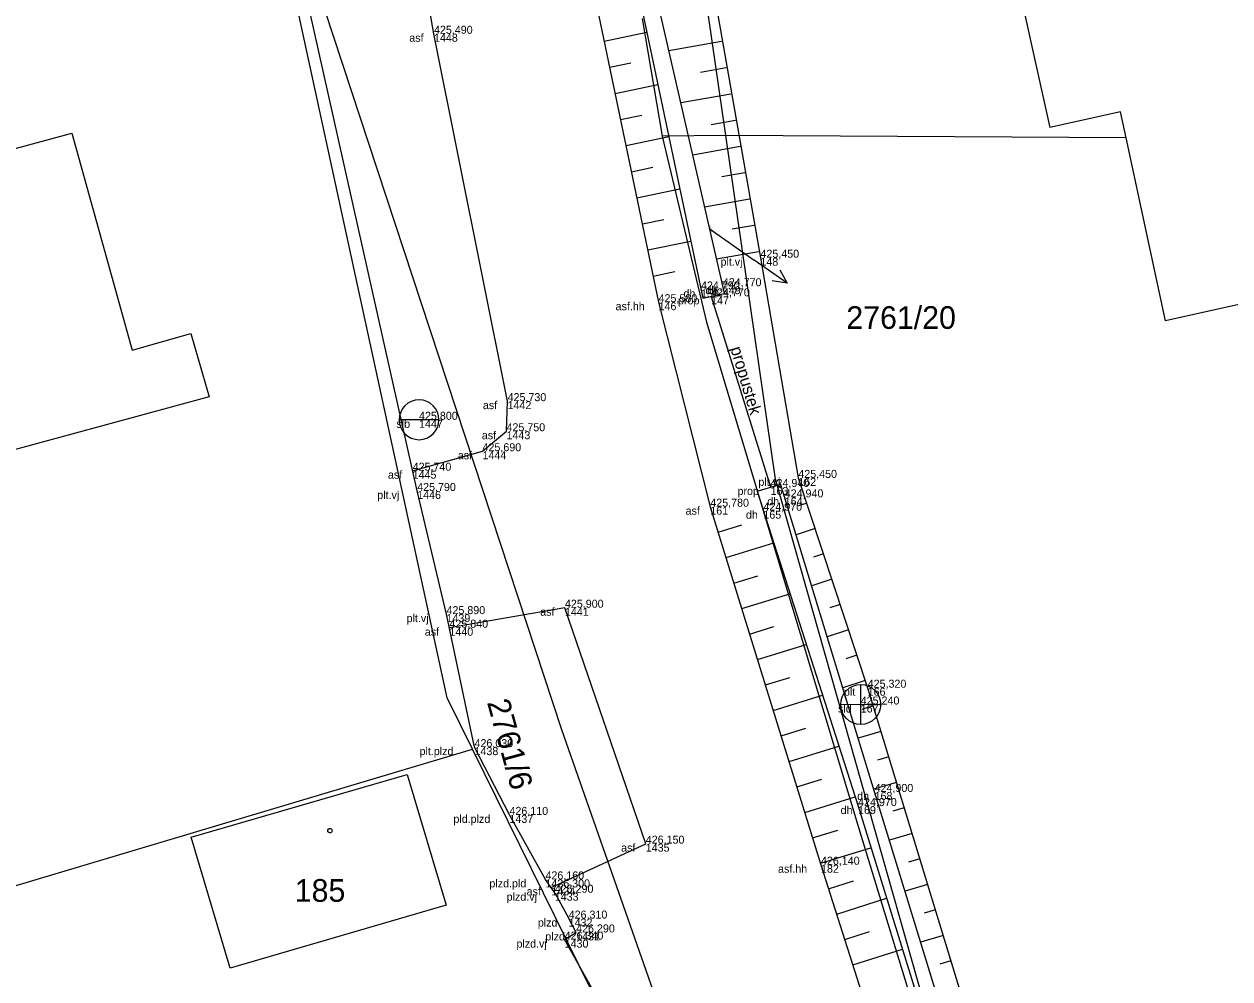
# Model space of a CAD drawing. Extents: x -747792 to -745414, y -1093712 to -1091463.
# Drawn here: x -746644.57 to -746599.36, y -1092850.41 to -1092814.6 of the extents above; entities that cross this region are included whole.
import ezdxf

# ---------------------------------------------------------------- set-up
doc = ezdxf.new("R2010")
doc.units = 0
for name, color, linetype in [('Doplňkové značky', 7, 'Continuous'), ('Hladina', 7, 'Continuous'), ('Koleje_dopravní prvky', 7, 'Continuous'), ('Nezařazené objekty', 7, 'Continuous'), ('Nivelační značky_hrany', 7, 'Continuous'), ('Ploty_opěrné zdi', 7, 'Continuous'), ('Pracovní_bod PPBP', 7, 'Continuous'), ('Pracovní_bod PPBP - výška', 7, 'Continuous'), ('Pracovní_bod ZPBP', 7, 'Continuous'), ('Pracovní_bod ZPBP - číslo', 7, 'Continuous'), ('Rozhraní ploch', 7, 'Continuous'), ('Stromy_porost', 7, 'Continuous'), ('Výškopis', 7, 'Continuous'), ('Čísla popisná_parcelní', 7, 'Continuous')]:
    doc.layers.add(name, color=color, linetype=linetype)

msp = doc.modelspace()

# ---------------------------------------------------------------- linework, layer by layer
at = {"layer": 'Doplňkové značky'}
for points in [[(-746618.85, -1092822.29), (-746617.19, -1092823.45)], [(-746615.963, -1092824.313), (-746617.19, -1092823.45)], [(-746616.228, -1092823.821), (-746615.963, -1092824.313), (-746616.516, -1092824.23)]]:
    msp.add_lwpolyline(points, dxfattribs=at)
at = {"layer": 'Hladina'}
for p, q in [((-746629.2, -1092814.96), (-746629.2, -1092814.96)), ((-746616.96, -1092823.36), (-746616.96, -1092823.36)), ((-746618.37, -1092824.43), (-746618.37, -1092824.43)), ((-746619.19, -1092824.55), (-746619.19, -1092824.55)), ((-746618.81, -1092824.81), (-746618.81, -1092824.81)), ((-746620.78, -1092825.03), (-746620.78, -1092825.03)), ((-746626.44, -1092828.74), (-746626.44, -1092828.74)), ((-746629.76, -1092829.44), (-746629.76, -1092829.44)), ((-746626.48, -1092829.87), (-746626.48, -1092829.87)), ((-746627.38, -1092830.62), (-746627.38, -1092830.62)), ((-746630, -1092831.35), (-746630, -1092831.35)), ((-746615.54, -1092831.62), (-746615.54, -1092831.62)), ((-746629.83, -1092832.11), (-746629.83, -1092832.11)), ((-746616.58, -1092831.96), (-746616.58, -1092831.96)), ((-746616.05, -1092832.35), (-746616.05, -1092832.35)), ((-746618.84, -1092832.7), (-746618.84, -1092832.7)), ((-746616.85, -1092832.85), (-746616.85, -1092832.85)), ((-746624.29, -1092836.49), (-746624.29, -1092836.49)), ((-746628.73, -1092836.73), (-746628.73, -1092836.73)), ((-746628.62, -1092837.24), (-746628.62, -1092837.24)), ((-746612.94, -1092839.49), (-746612.94, -1092839.49)), ((-746613.2, -1092840.12), (-746613.2, -1092840.12)), ((-746627.68, -1092841.72), (-746627.68, -1092841.72)), ((-746612.68, -1092843.4), (-746612.68, -1092843.4)), ((-746626.37, -1092844.26), (-746626.37, -1092844.26)), ((-746613.3, -1092843.93), (-746613.3, -1092843.93)), ((-746621.26, -1092845.34), (-746621.26, -1092845.34)), ((-746614.69, -1092846.13), (-746614.69, -1092846.13)), ((-746625.02, -1092846.68), (-746625.02, -1092846.68)), ((-746624.8, -1092846.98), (-746624.8, -1092846.98)), ((-746624.67, -1092847.18), (-746624.67, -1092847.18)), ((-746624.15, -1092848.15), (-746624.15, -1092848.15)), ((-746623.87, -1092848.67), (-746623.87, -1092848.67)), ((-746624.3, -1092848.94), (-746624.3, -1092848.94))]:
    msp.add_line(p, q, dxfattribs=at)
at = {"layer": 'Nezařazené objekty'}
for points in [[(-746624.2, -1092782.38), (-746620.59, -1092802.65), (-746616.96, -1092823.36)], [(-746629.83, -1092832.11), (-746635.92, -1092804.9), (-746640.61, -1092805.95)], [(-746619.12, -1092824.88), (-746618.31, -1092824.7)], [(-746615.54, -1092831.62), (-746612.94, -1092839.49), (-746608.13, -1092855.28), (-746607.03, -1092859.03)], [(-746617.08, -1092832.12), (-746616.2, -1092831.85)], [(-746627.68, -1092841.72), (-746628.73, -1092836.73)], [(-746626.37, -1092844.26), (-746627.68, -1092841.72)], [(-746625.02, -1092846.68), (-746626.37, -1092844.26)], [(-746624.67, -1092847.18), (-746625.02, -1092846.68)], [(-746624.3, -1092848.94), (-746623.87, -1092848.67), (-746624.15, -1092848.15)]]:
    msp.add_lwpolyline(points, dxfattribs=at)
at = {"layer": 'Nivelační značky_hrany'}
for points in [[(-746627.15, -1092784.02), (-746627.36, -1092786.44), (-746626.8, -1092790.33), (-746625.27, -1092801.07), (-746623.33, -1092812.79), (-746620.78, -1092825.03)], [(-746630, -1092831.35), (-746627.38, -1092830.62), (-746626.48, -1092829.87), (-746626.44, -1092828.74), (-746629.2, -1092814.96), (-746631.2, -1092803.41), (-746631.6, -1092801.51)], [(-746620.78, -1092825.03), (-746618.84, -1092832.7)], [(-746618.84, -1092832.7), (-746614.69, -1092846.13), (-746610.21, -1092860.22)], [(-746624.8, -1092846.98), (-746621.26, -1092845.34), (-746624.29, -1092836.49), (-746628.62, -1092837.24)]]:
    msp.add_lwpolyline(points, dxfattribs=at)
at = {"layer": 'Ploty_opěrné zdi'}
msp.add_lwpolyline([(-746633.1, -1092844.765), (-746633.05, -1092844.775), (-746633.025, -1092844.82), (-746633.015, -1092844.85), (-746633.025, -1092844.895), (-746633.065, -1092844.93), (-746633.1, -1092844.935), (-746633.145, -1092844.92), (-746633.175, -1092844.89), (-746633.185, -1092844.85), (-746633.175, -1092844.805), (-746633.135, -1092844.77)], close=True, dxfattribs=at)
at = {"layer": 'Pracovní_bod PPBP'}
for points in [[(-746626.71, -1092783.97), (-746625.36, -1092789.94), (-746623.69, -1092800.76), (-746621.37, -1092814.2), (-746619.121, -1092824.876)], [(-746618.309, -1092824.695), (-746620.8, -1092813.84), (-746621.31, -1092810.82), (-746622.95, -1092800.4), (-746624.71, -1092789.67), (-746624.97, -1092783.83)], [(-746622.816, -1092815.239), (-746621.221, -1092814.906)], [(-746618.415, -1092815.255), (-746620.395, -1092815.604)], [(-746622.612, -1092816.217), (-746621.814, -1092816.051)], [(-746618.241, -1092816.24), (-746619.206, -1092816.41)], [(-746622.408, -1092817.196), (-746620.809, -1092816.863)], [(-746618.068, -1092817.225), (-746619.947, -1092817.556)], [(-746622.204, -1092818.175), (-746621.403, -1092818.008)], [(-746617.894, -1092818.21), (-746618.809, -1092818.371)], [(-746622, -1092819.154), (-746620.397, -1092818.82)], [(-746617.721, -1092819.194), (-746619.499, -1092819.508)], [(-746621.796, -1092820.133), (-746620.993, -1092819.966)], [(-746617.547, -1092820.179), (-746618.411, -1092820.331)], [(-746621.591, -1092821.112), (-746619.985, -1092820.777)], [(-746617.374, -1092821.164), (-746619.052, -1092821.46)], [(-746621.387, -1092822.091), (-746620.583, -1092821.923)], [(-746617.201, -1092822.149), (-746618.014, -1092822.292)], [(-746621.183, -1092823.07), (-746619.572, -1092822.734)], [(-746617.027, -1092823.134), (-746618.604, -1092823.411)], [(-746620.979, -1092824.049), (-746620.173, -1092823.881)], [(-746617.084, -1092832.121), (-746613.3, -1092843.93), (-746609.67, -1092855.65), (-746608.74, -1092859.8)], [(-746607.95, -1092859.56), (-746609.06, -1092855.21), (-746612.68, -1092843.4), (-746616.204, -1092831.845)], [(-746615.226, -1092832.57), (-746615.57, -1092832.683)], [(-746618.545, -1092833.655), (-746617.656, -1092833.381)], [(-746614.913, -1092833.519), (-746615.622, -1092833.753)], [(-746618.25, -1092834.611), (-746616.463, -1092834.059)], [(-746614.599, -1092834.469), (-746614.965, -1092834.589)], [(-746617.954, -1092835.566), (-746617.056, -1092835.289)], [(-746614.285, -1092835.418), (-746615.038, -1092835.667)], [(-746617.659, -1092836.522), (-746615.852, -1092835.963)], [(-746613.972, -1092836.368), (-746614.359, -1092836.496)], [(-746617.364, -1092837.477), (-746616.456, -1092837.196)], [(-746613.658, -1092837.317), (-746614.455, -1092837.58)], [(-746617.069, -1092838.433), (-746615.242, -1092837.868)], [(-746613.344, -1092838.267), (-746613.754, -1092838.402)], [(-746616.773, -1092839.388), (-746615.855, -1092839.104)], [(-746613.03, -1092839.216), (-746613.871, -1092839.494)], [(-746616.478, -1092840.343), (-746614.632, -1092839.773)], [(-746612.733, -1092840.171), (-746613.159, -1092840.301)], [(-746616.183, -1092841.299), (-746615.255, -1092841.012)], [(-746612.441, -1092841.127), (-746613.294, -1092841.387)], [(-746615.888, -1092842.254), (-746614.022, -1092841.678)], [(-746612.15, -1092842.084), (-746612.576, -1092842.214)], [(-746615.592, -1092843.21), (-746614.654, -1092842.92)], [(-746611.858, -1092843.041), (-746612.71, -1092843.3)], [(-746615.297, -1092844.165), (-746613.411, -1092843.582)], [(-746611.567, -1092843.997), (-746611.992, -1092844.127)], [(-746615.002, -1092845.121), (-746614.057, -1092844.829)], [(-746611.276, -1092844.954), (-746612.124, -1092845.212)], [(-746614.707, -1092846.076), (-746612.816, -1092845.492)], [(-746610.984, -1092845.91), (-746611.408, -1092846.039)], [(-746614.404, -1092847.029), (-746613.465, -1092846.73)], [(-746610.693, -1092846.867), (-746611.538, -1092847.125)], [(-746614.101, -1092847.982), (-746612.229, -1092847.387)], [(-746610.401, -1092847.824), (-746610.823, -1092847.952)], [(-746613.798, -1092848.935), (-746612.866, -1092848.639)], [(-746610.11, -1092848.78), (-746610.952, -1092849.037)], [(-746613.495, -1092849.888), (-746611.638, -1092849.297)], [(-746609.819, -1092849.737), (-746610.239, -1092849.865)]]:
    msp.add_lwpolyline(points, dxfattribs=at)
at = {"layer": 'Pracovní_bod PPBP - výška'}
for points in [[(-746616.96, -1092823.36), (-746615.54, -1092831.62)], [(-746628.73, -1092836.73), (-746629.83, -1092832.11)], [(-746624.67, -1092847.18), (-746624.15, -1092848.15)], [(-746622.4, -1092852.33), (-746624.3, -1092848.94)]]:
    msp.add_lwpolyline(points, dxfattribs=at)
at = {"layer": 'Pracovní_bod ZPBP'}
msp.add_lwpolyline([(-746618.81, -1092824.81), (-746616.58, -1092831.96)], dxfattribs=at)
at = {"layer": 'Stromy_porost'}
for points in [[(-746618.26, -1092818.78), (-746620.6, -1092802.62)], [(-746636.26, -1092805.07), (-746624.42, -1092841.06)], [(-746628.71, -1092839.87), (-746636.26, -1092805.07)], [(-746609.03, -1092805.29), (-746606.11, -1092818.48)], [(-746621.4, -1092814.39), (-746620.65, -1092818.8)], [(-746603.46, -1092817.89), (-746606.11, -1092818.48)], [(-746603.25, -1092818.87), (-746603.46, -1092817.89)], [(-746618.26, -1092818.78), (-746620.65, -1092818.8)], [(-746620.65, -1092818.8), (-746618.98, -1092825.78)], [(-746603.25, -1092818.87), (-746618.26, -1092818.78)], [(-746616.4, -1092831.67), (-746618.26, -1092818.78)], [(-746601.77, -1092825.73), (-746603.25, -1092818.87)], [(-746593.69, -1092823.93), (-746601.77, -1092825.73)], [(-746618.98, -1092825.78), (-746613.27, -1092844.77)], [(-746605.01, -1092871.84), (-746616.4, -1092831.67)], [(-746627.76, -1092841.79), (-746628.71, -1092839.87)], [(-746624.42, -1092841.06), (-746615.33, -1092867)], [(-746679.02, -1092857.11), (-746627.76, -1092841.79)], [(-746615.33, -1092867), (-746627.76, -1092841.79)], [(-746638.3, -1092845.1), (-746630.2, -1092842.74)], [(-746630.2, -1092842.74), (-746628.74, -1092847.65)], [(-746613.27, -1092844.77), (-746605.01, -1092871.84)], [(-746636.84, -1092850.01), (-746638.3, -1092845.1)], [(-746628.74, -1092847.65), (-746636.84, -1092850.01)]]:
    msp.add_lwpolyline(points, dxfattribs=at)
msp.add_lwpolyline([(-746651.78, -1092821.13), (-746642.78, -1092818.69), (-746640.51, -1092826.83), (-746638.31, -1092826.2), (-746637.63, -1092828.58), (-746646.65, -1092831.03), (-746647.9, -1092826.52), (-746650.12, -1092827.13)], close=True, dxfattribs=at)
at = {"layer": 'Čísla popisná_parcelní'}
for p, q in [((-746629.013, -1092829.44), (-746630.508, -1092829.44)), ((-746613.201, -1092840.868), (-746613.2, -1092839.373)), ((-746612.448, -1092840.126), (-746613.948, -1092840.121))]:
    msp.add_line(p, q, dxfattribs=at)
msp.add_circle((-746613.2, -1092840.12), 0.75, dxfattribs=at)
for start, end in [(0, 180), (180, 0)]:
    msp.add_arc((-746629.76, -1092829.44), 0.747, start, end, dxfattribs=at)

# ---------------------------------------------------------------- texts
at = {"layer": 'Doplňkové značky'}
msp.add_text('2761/20', height=0.85, dxfattribs=at).set_placement((-746613.74, -1092826.03))
at = {"layer": 'Koleje_dopravní prvky'}
for s, height, rotation, p in [('2761/20', 0.05, 279.4888, (-746618.872, -1092822.157)), ('2761/6', 0.85, 285.4476, (-746627.217, -1092840.035))]:
    msp.add_text(s, height=height, rotation=rotation, dxfattribs=at).set_placement(p)
msp.add_text('185', height=0.85, dxfattribs=at).set_placement((-746634.42, -1092847.52))
at = {"layer": 'Pracovní_bod ZPBP - číslo'}
msp.add_text('propustek', height=0.45, rotation=286.5409, dxfattribs=at).set_placement((-746618.091, -1092826.76))
at = {"layer": 'Rozhraní ploch'}
for s, p in [(' asf', (-746630.237, -1092815.26)), ('1448', (-746629.2, -1092815.26)), (' plt.vj', (-746618.568, -1092823.66)), ('148', (-746616.96, -1092823.66)), (' dh', (-746619.135, -1092824.73)), ('149', (-746618.37, -1092824.73)), (' prop', (-746620.161, -1092825.11)), (' dh', (-746619.955, -1092824.85)), ('150', (-746619.19, -1092824.85)), ('147', (-746618.81, -1092825.11)), (' asf.hh', (-746622.502, -1092825.33)), ('146', (-746620.78, -1092825.33)), (' asf', (-746627.477, -1092829.04)), ('1442', (-746626.44, -1092829.04)), (' slb', (-746630.721, -1092829.74)), ('1447', (-746629.76, -1092829.74)), (' asf', (-746627.517, -1092830.17)), ('1443', (-746626.48, -1092830.17)), (' asf', (-746628.417, -1092830.92)), ('1444', (-746627.38, -1092830.92)), (' asf', (-746631.037, -1092831.65)), ('1445', (-746630, -1092831.65)), (' plt.vj', (-746617.148, -1092831.92)), ('162', (-746615.54, -1092831.92)), (' plt.vj', (-746631.438, -1092832.41)), ('1446', (-746629.83, -1092832.41)), (' prop', (-746617.931, -1092832.26)), ('163', (-746616.58, -1092832.26)), (' dh', (-746616.815, -1092832.65)), ('164', (-746616.05, -1092832.65)), (' asf', (-746619.877, -1092833)), ('161', (-746618.84, -1092833)), (' dh', (-746617.615, -1092833.15)), ('165', (-746616.85, -1092833.15)), (' asf', (-746625.327, -1092836.79)), ('1441', (-746624.29, -1092836.79)), (' plt.vj', (-746630.338, -1092837.03)), ('1439', (-746628.73, -1092837.03)), (' asf', (-746629.657, -1092837.54)), ('1440', (-746628.62, -1092837.54)), (' plt', (-746613.939, -1092839.79)), ('166', (-746612.94, -1092839.79)), (' sld', (-746614.161, -1092840.42)), ('167', (-746613.2, -1092840.42)), (' plt.plzd', (-746629.853, -1092842.02)), ('1438', (-746627.68, -1092842.02)), (' dh', (-746613.445, -1092843.7)), ('168', (-746612.68, -1092843.7)), (' dh', (-746614.065, -1092844.23)), (' pld.plzd', (-746628.583, -1092844.56)), ('1437', (-746626.37, -1092844.56)), ('169', (-746613.3, -1092844.23)), (' asf', (-746622.297, -1092845.64)), ('1435', (-746621.26, -1092845.64)), (' asf.hh', (-746616.412, -1092846.43)), ('182', (-746614.69, -1092846.43)), (' plzd.pld', (-746627.233, -1092846.98)), (' asf', (-746625.837, -1092847.28)), ('1436', (-746625.02, -1092846.98)), ('1434', (-746624.8, -1092847.28)), (' plzd.vj', (-746626.588, -1092847.48)), ('1433', (-746624.67, -1092847.48)), (' plzd', (-746625.418, -1092848.45)), ('1432', (-746624.15, -1092848.45)), (' plzd', (-746625.138, -1092848.97)), ('1431', (-746623.87, -1092848.97)), (' plzd.vj', (-746626.218, -1092849.24)), ('1430', (-746624.3, -1092849.24))]:
    msp.add_text(s, height=0.3, dxfattribs=at).set_placement(p)
at = {"layer": 'Výškopis'}
for s, p in [('425,490', (-746629.2, -1092814.96)), ('425,450', (-746616.96, -1092823.36)), ('424,790', (-746619.19, -1092824.55)), ('424,770', (-746618.37, -1092824.43)), ('425,580', (-746620.78, -1092825.03)), ('424,770', (-746618.81, -1092824.81)), ('425,730', (-746626.44, -1092828.74)), ('425,800', (-746629.76, -1092829.44)), ('425,750', (-746626.48, -1092829.87)), ('425,690', (-746627.38, -1092830.62)), ('425,740', (-746630, -1092831.35)), ('424,940', (-746616.58, -1092831.96)), ('425,450', (-746615.54, -1092831.62)), ('425,790', (-746629.83, -1092832.11)), ('424,940', (-746616.05, -1092832.35)), ('425,780', (-746618.84, -1092832.7)), ('424,970', (-746616.85, -1092832.85)), ('425,900', (-746624.29, -1092836.49)), ('425,890', (-746628.73, -1092836.73)), ('425,840', (-746628.62, -1092837.24)), ('425,320', (-746612.94, -1092839.49)), ('425,240', (-746613.2, -1092840.12)), ('426,030', (-746627.68, -1092841.72)), ('424,900', (-746612.68, -1092843.4)), ('424,970', (-746613.3, -1092843.93)), ('426,110', (-746626.37, -1092844.26)), ('426,150', (-746621.26, -1092845.34)), ('426,140', (-746614.69, -1092846.13)), ('426,160', (-746625.02, -1092846.68)), ('426,300', (-746624.8, -1092846.98)), ('426,290', (-746624.67, -1092847.18)), ('426,310', (-746624.15, -1092848.15)), ('426,290', (-746623.87, -1092848.67)), ('426,340', (-746624.3, -1092848.94))]:
    msp.add_text(s, height=0.3, dxfattribs=at).set_placement(p)

doc.saveas('drawing.dxf')
